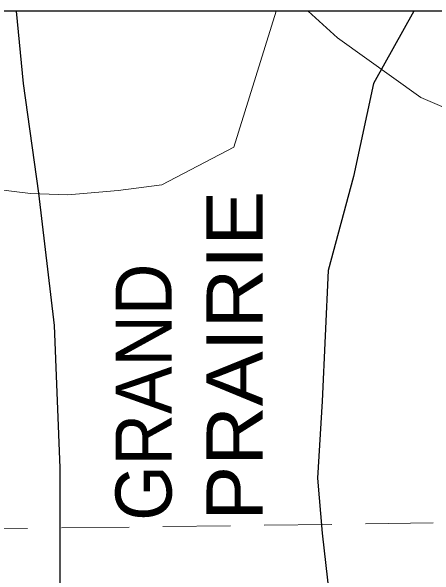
# Model space of a CAD drawing. Extents: x 2363323 to 2367082, y 6956018 to 6980837.
# Drawn here: x 2365987.3 to 2366064.3, y 6980732.7 to 6980835.5 of the extents above; entities that cross this region are included whole.
import ezdxf

# ---------------------------------------------------------------- set-up
doc = ezdxf.new("R2010")
doc.units = 0
doc.header["$LTSCALE"] = 4.1
doc.linetypes.add('MEDIUM_DASHED', pattern=[4.5, 3, -1.5])
doc.layers.add('62', color=7, linetype='Continuous', lineweight=13)
doc.layers.add('63', color=7, linetype='Continuous', lineweight=13)

msp = doc.modelspace()

# ---------------------------------------------------------------- linework, layer by layer
at = {"layer": '62', "linetype": 'MEDIUM_DASHED'}
msp.add_line((2365848.822, 6980739.484), (2366129.802, 6980743.218), dxfattribs=at)
at = {"layer": '62', "lineweight": 25}
for points in [[(2365753.976, 6980385.954), (2366219.249, 6980385.954), (2366219.249, 6980835.546), (2365753.974, 6980835.546)], [(2365988.154, 6980835.546), (2365989.437, 6980822.404), (2365992.248, 6980802.402), (2365995.06, 6980778.345), (2365996.118, 6980752.4), (2365996.118, 6980723.35), (2365996.997, 6980691.422), (2365998.12, 6980673.24)], [(2366060.542, 6980835.548), (2366053.23, 6980822.404), (2366049.539, 6980805.483), (2366044.949, 6980788.336), (2366043.892, 6980764.532), (2366043.014, 6980750.487), (2366043.892, 6980740.474), (2366045.825, 6980723.35), (2366045.826, 6980711.446), (2366046.412, 6980702.514)]]:
    msp.add_lwpolyline(points, dxfattribs=at)
at = {"layer": '62'}
for points in [[(2366035.476, 6980835.546), (2366032.618, 6980826.432), (2366027.778, 6980810.793), (2366014.661, 6980803.953), (2366006.718, 6980802.918), (2365997.558, 6980802.086), (2365990.808, 6980802.356), (2365983.294, 6980803.3), (2365976.588, 6980802.579), (2365967.36, 6980802.74)], [(2366041.328, 6980835.544), (2366046.682, 6980830.731), (2366061.803, 6980819.864), (2366077.847, 6980812.974)]]:
    msp.add_lwpolyline(points, dxfattribs=at)
at = {"layer": '63', "linetype": 'MEDIUM_DASHED'}
msp.add_line((2365848.822, 6980739.484), (2366129.802, 6980743.218), dxfattribs=at)
at = {"layer": '63', "lineweight": 25}
for points in [[(2365753.976, 6980385.954), (2366219.249, 6980385.954), (2366219.249, 6980835.546), (2365753.974, 6980835.546)], [(2365988.154, 6980835.546), (2365989.437, 6980822.404), (2365992.248, 6980802.402), (2365995.06, 6980778.345), (2365996.118, 6980752.4), (2365996.118, 6980723.35), (2365996.997, 6980691.422), (2365998.12, 6980673.24)], [(2366060.542, 6980835.548), (2366053.23, 6980822.404), (2366049.539, 6980805.483), (2366044.949, 6980788.336), (2366043.892, 6980764.532), (2366043.014, 6980750.487), (2366043.892, 6980740.474), (2366045.825, 6980723.35), (2366045.826, 6980711.446), (2366046.412, 6980702.514)]]:
    msp.add_lwpolyline(points, dxfattribs=at)
at = {"layer": '63'}
for points in [[(2366035.476, 6980835.546), (2366032.618, 6980826.432), (2366027.778, 6980810.793), (2366014.661, 6980803.953), (2366006.718, 6980802.918), (2365997.558, 6980802.086), (2365990.808, 6980802.356), (2365983.294, 6980803.3), (2365976.588, 6980802.579), (2365967.36, 6980802.74)], [(2366041.328, 6980835.544), (2366046.682, 6980830.731), (2366061.803, 6980819.864), (2366077.847, 6980812.974)]]:
    msp.add_lwpolyline(points, dxfattribs=at)

# ---------------------------------------------------------------- texts
at = {"layer": '62'}
for s, width, p in [('PRAIRIE', 1.1, (2366033.021, 6980742.747)), ('GRAND', 0.95, (2366016.461, 6980742.747))]:
    msp.add_text(s, height=10.21, rotation=90, dxfattribs=dict(at, width=width)).set_placement(p)
at = {"layer": '63'}
for s, width, p in [('PRAIRIE', 1.1, (2366033.021, 6980742.747)), ('GRAND', 0.95, (2366016.461, 6980742.747))]:
    msp.add_text(s, height=10.21, rotation=90, dxfattribs=dict(at, width=width)).set_placement(p)

doc.saveas('drawing.dxf')
